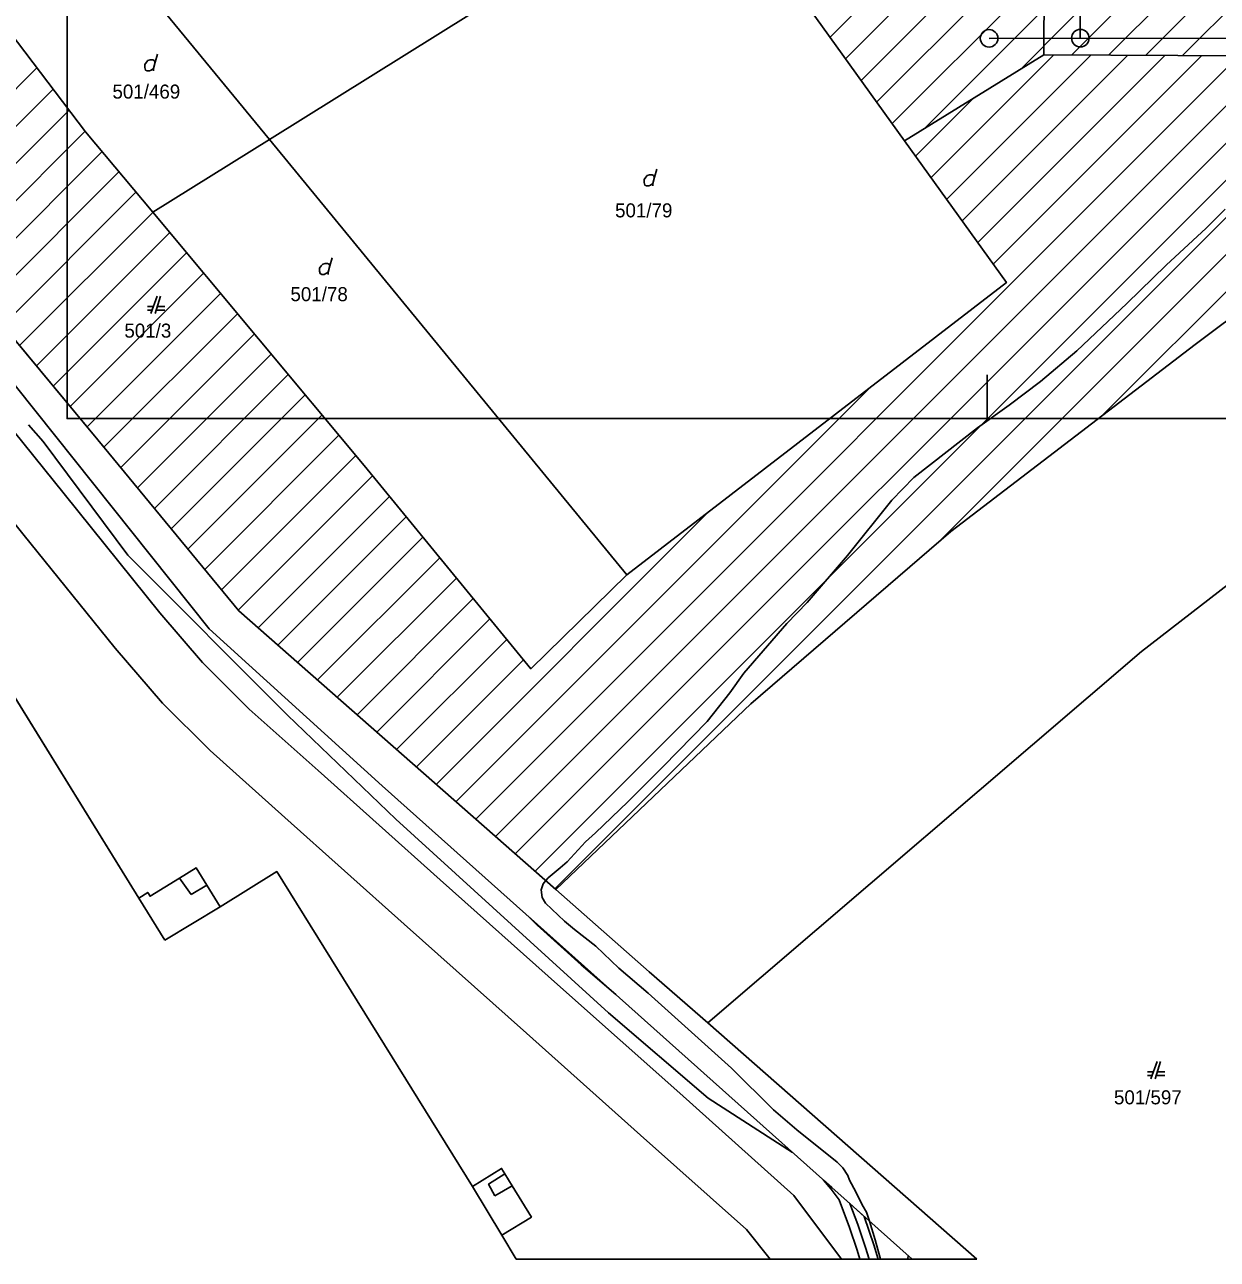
# Model space of a CAD drawing. Extents: x -264309 to -263505, y -1242443 to -1241763.
# Drawn here: x -264215.7 to -264079.6, y -1242443.4 to -1242302.6 of the extents above; entities that cross this region are included whole.
import ezdxf

# ---------------------------------------------------------------- set-up
doc = ezdxf.new("R2010")
doc.units = 0
for name, color, linetype in [('KFA_DAZDOVA_KANALIZACIA_vetva_D', 7, 'Continuous'), ('KFA_DAZDOVA_KANALIZACIA_vetva_F', 7, 'Continuous'), ('KN_2019_08_16', 7, 'Continuous'), ('KN_2019_08_16_KLADPAR', 7, 'Continuous'), ('KN_2019_08_16_ZAPPAR', 7, 'Continuous'), ('RAM_NA_TLAC_10xA4_1-500', 7, 'Continuous'), ('SRAFY_PARCELY', 7, 'Continuous')]:
    doc.layers.add(name, color=color, linetype=linetype)

msp = doc.modelspace()

# ---------------------------------------------------------------- linework, layer by layer
at = {"layer": 'KFA_DAZDOVA_KANALIZACIA_vetva_D'}
msp.add_lwpolyline([(-263821.59, -1242304.45), (-263853.82, -1242304.12), (-263903.79, -1242304.32), (-263951.83, -1242303.9), (-264004.17, -1242304.05), (-264044.82, -1242304.22), (-264095.21, -1242304.15), (-264105.62, -1242304.17)], dxfattribs=at)
for centre in [(-264105.62, -1242304.17), (-264095.21, -1242304.15)]:
    msp.add_circle(centre, 1, dxfattribs=at)
at = {"layer": 'KFA_DAZDOVA_KANALIZACIA_vetva_F'}
msp.add_lwpolyline([(-264123.84, -1242298.32), (-264095.25, -1242298.17), (-264095.21, -1242304.15)], dxfattribs=at)
at = {"layer": 'KN_2019_08_16'}
for points in [[(-264119.28, -1242439.08), (-264119.6, -1242438.07), (-264120.12, -1242437.23), (-264120.84, -1242435.74), (-264121.56, -1242434.41), (-264121.75, -1242433.87), (-264122.32, -1242433.02), (-264122.94, -1242432.35), (-264127.57, -1242428.67), (-264130.23, -1242426.38), (-264135.02, -1242421.64), (-264144.52, -1242413.09), (-264147.87, -1242410.23), (-264150.5, -1242407.72), (-264152.93, -1242405.83), (-264154.08, -1242404.89), (-264156.24, -1242402.81), (-264156.6, -1242402.17), (-264156.73, -1242401.31), (-264156.51, -1242400.61), (-264156.21, -1242400.25), (-264155.92, -1242399.93), (-264154.58, -1242398.8), (-264153.78, -1242398.09), (-264151.67, -1242395.84), (-264150.54, -1242394.8), (-264146.83, -1242391.28), (-264142.81, -1242387.25), (-264137.8, -1242382.11), (-264135.2, -1242378.82), (-264133.61, -1242376.59), (-264128.69, -1242370.91), (-264126.36, -1242368.51), (-264121.76, -1242363.16), (-264116.7, -1242356.85), (-264114.2, -1242354.26), (-264106.94, -1242348.61), (-264103.34, -1242346.03), (-264099.74, -1242343.3), (-264095.59, -1242339.81), (-264089.92, -1242334.43), (-264085.4, -1242330.05), (-264080.85, -1242325.81), (-264078.68, -1242323.64)], [(-264128.04, -1242431.26), (-264137.67, -1242425.08), (-264149.03, -1242415.35), (-264173.32, -1242393.23), (-264185.68, -1242381.36), (-264203.89, -1242363.13), (-264213.57, -1242350.16), (-264215.24, -1242348.24)], [(-264120.36, -1242443.45), (-264120.66, -1242442.41), (-264121.53, -1242439.81), (-264122.74, -1242436.68), (-264123.65, -1242435.44), (-264124.5, -1242434.42), (-264123.56, -1242435.26), (-264121.52, -1242437.08), (-264119.87, -1242438.56), (-264118.76, -1242441.81), (-264118.28, -1242443.45)], [(-264119.32, -1242443.45), (-264119.71, -1242442.11), (-264120.59, -1242439.47), (-264121.52, -1242437.08)], [(-264118, -1242443.45), (-264118.6, -1242441.21), (-264119.28, -1242439.08)], [(-264114.9, -1242443.45), (-264114.86, -1242443.03)]]:
    msp.add_lwpolyline(points, dxfattribs=at)
msp.add_lwpolyline([(-264148.21, -1242413.25), (-264152.18, -1242409.86), (-264157.18, -1242405.35), (-264158.21, -1242404.32)], close=True, dxfattribs=at)
at = {"layer": 'KN_2019_08_16_KLADPAR'}
for p, q in [((-264200.79, -1242306.88), (-264200.52, -1242305.98)), ((-264240.46, -1242310.08), (-264207.32, -1242349.97)), ((-264194.62, -1242371.54), (-264240.44, -1242314.08)), ((-264240.44, -1242314.08), (-264194.62, -1242371.54)), ((-264143.81, -1242320), (-264143.54, -1242319.1)), ((-264180.85, -1242330.11), (-264180.58, -1242329.21)), ((-264200.56, -1242333.56), (-264201.26, -1242335.56)), ((-264200.76, -1242335.56), (-264200.16, -1242333.56)), ((-264200.98, -1242334.76), (-264201.66, -1242334.76)), ((-264199.66, -1242334.76), (-264200.52, -1242334.76)), ((-264201.66, -1242335.16), (-264201.12, -1242335.16)), ((-264200.64, -1242335.16), (-264199.66, -1242335.16)), ((-264207.32, -1242349.97), (-264191.23, -1242369.48)), ((-264202.64, -1242402.25), (-264234.16, -1242351.24)), ((-264191.23, -1242369.48), (-264155.07, -1242401.25)), ((-264174.88, -1242389.44), (-264194.62, -1242371.54)), ((-264194.62, -1242371.54), (-264174.88, -1242389.44)), ((-264123.56, -1242435.26), (-264174.88, -1242389.44)), ((-264174.88, -1242389.44), (-264123.56, -1242435.26)), ((-264196.09, -1242398.8), (-264198, -1242399.97)), ((-264194.88, -1242400.75), (-264196.09, -1242398.8)), ((-264186.9, -1242399.22), (-264193.34, -1242403.23)), ((-264164.58, -1242435.14), (-264186.9, -1242399.22)), ((-264198, -1242399.97), (-264201.36, -1242402.03)), ((-264193.34, -1242403.23), (-264194.88, -1242400.75)), ((-264155.07, -1242401.25), (-264144.39, -1242410.64)), ((-264201.63, -1242401.6), (-264202.64, -1242402.25)), ((-264201.36, -1242402.03), (-264201.63, -1242401.6)), ((-264144.39, -1242410.64), (-264137.73, -1242416.49)), ((-264137.73, -1242416.49), (-264107.02, -1242443.45)), ((-264086.45, -1242420.88), (-264087.15, -1242422.88)), ((-264086.65, -1242422.88), (-264086.05, -1242420.88)), ((-264086.87, -1242422.08), (-264087.55, -1242422.08)), ((-264085.55, -1242422.08), (-264086.41, -1242422.08)), ((-264087.55, -1242422.48), (-264087.01, -1242422.48)), ((-264086.53, -1242422.48), (-264085.55, -1242422.48)), ((-264161.25, -1242433.08), (-264164.58, -1242435.14)), ((-264160.87, -1242433.7), (-264161.25, -1242433.08)), ((-264160.03, -1242435.07), (-264160.87, -1242433.7)), ((-264157.85, -1242438.64), (-264160.03, -1242435.07)), ((-264114.39, -1242443.45), (-264123.56, -1242435.26)), ((-264123.56, -1242435.26), (-264114.39, -1242443.45)), ((-264161.23, -1242440.7), (-264157.85, -1242438.64)), ((-264159.6, -1242443.45), (-264161.23, -1242440.7)), ((-264114.39, -1242443.45), (-264159.6, -1242443.45)), ((-264107.02, -1242443.45), (-264114.39, -1242443.45))]:
    msp.add_line(p, q, dxfattribs=at)
for points in [[(-264212.29, -1242180.92), (-264215.03, -1242177.17), (-264211.96, -1242175.6), (-264195.05, -1242168.92), (-264177.6, -1242192.97), (-264074.04, -1242162.41), (-264070.8, -1242196.19), (-264098.84, -1242196.05), (-264099.36, -1242306.05), (-264115.27, -1242315.84), (-264137.78, -1242284.52)], [(-264264.01, -1242217.15), (-264233.51, -1242192.88), (-264212.29, -1242180.92), (-264137.78, -1242284.52), (-264187.74, -1242315.7), (-264213.92, -1242283.84)], [(-263950.84, -1242196.76), (-263951.29, -1242290.6), (-263951.37, -1242306.76), (-264045.86, -1242306.31), (-264099.36, -1242306.05), (-264098.84, -1242196.05), (-264070.8, -1242196.19)], [(-264187.74, -1242315.7), (-264201.06, -1242324.01), (-264208.73, -1242314.82), (-264233.72, -1242281.89), (-264276.4, -1242228.3), (-264264.01, -1242217.15), (-264213.92, -1242283.84)], [(-264187.74, -1242315.7), (-264137.78, -1242284.52), (-264115.27, -1242315.84), (-264103.64, -1242332.03), (-264146.94, -1242365.35)], [(-264187.74, -1242315.7), (-264146.94, -1242365.35), (-264157.91, -1242376.09), (-264176.92, -1242352.91), (-264201.06, -1242324.01)]]:
    msp.add_lwpolyline(points, close=True, dxfattribs=at)
for points in [[(-264155.07, -1242401.25), (-264191.23, -1242369.48), (-264207.32, -1242349.97), (-264240.46, -1242310.08), (-264272.98, -1242263.62)], [(-264233.72, -1242281.89), (-264208.73, -1242314.82), (-264201.06, -1242324.01), (-264176.92, -1242352.91), (-264157.91, -1242376.09), (-264146.94, -1242365.35), (-264103.64, -1242332.03), (-264115.27, -1242315.84), (-264099.36, -1242306.05), (-264045.86, -1242306.31)], [(-264200.97, -1242307.87), (-264200.97, -1242307.6), (-264200.79, -1242306.88), (-264200.88, -1242306.7), (-264201.06, -1242306.61), (-264201.33, -1242306.61), (-264201.6, -1242306.7), (-264201.78, -1242306.88), (-264201.96, -1242307.15), (-264201.96, -1242307.51), (-264201.87, -1242307.78), (-264201.69, -1242307.87), (-264201.42, -1242307.87), (-264201.24, -1242307.78), (-264200.97, -1242307.6)], [(-264143.99, -1242320.99), (-264143.99, -1242320.72), (-264143.81, -1242320), (-264143.9, -1242319.82), (-264144.08, -1242319.73), (-264144.35, -1242319.73), (-264144.62, -1242319.82), (-264144.8, -1242320), (-264144.98, -1242320.27), (-264144.98, -1242320.63), (-264144.89, -1242320.9), (-264144.71, -1242320.99), (-264144.44, -1242320.99), (-264144.26, -1242320.9), (-264143.99, -1242320.72)], [(-264155.07, -1242401.25), (-264132.82, -1242380.09), (-264109.99, -1242360.41), (-264082.11, -1242339.09), (-264061.82, -1242323.92)], [(-264061.82, -1242323.92), (-264082.11, -1242339.09), (-264109.99, -1242360.41), (-264132.82, -1242380.09), (-264155.07, -1242401.25)], [(-264181.03, -1242331.1), (-264181.03, -1242330.83), (-264180.85, -1242330.11), (-264180.94, -1242329.93), (-264181.12, -1242329.84), (-264181.39, -1242329.84), (-264181.66, -1242329.93), (-264181.84, -1242330.11), (-264182.02, -1242330.38), (-264182.02, -1242330.74), (-264181.93, -1242331.01), (-264181.75, -1242331.1), (-264181.48, -1242331.1), (-264181.3, -1242331.01), (-264181.03, -1242330.83)], [(-264234.16, -1242351.24), (-264202.64, -1242402.25), (-264201.63, -1242401.6), (-264201.36, -1242402.03), (-264198, -1242399.97), (-264196.09, -1242398.8), (-264194.88, -1242400.75), (-264193.34, -1242403.23), (-264186.9, -1242399.22), (-264164.58, -1242435.14), (-264161.25, -1242433.08), (-264160.87, -1242433.7), (-264160.03, -1242435.07), (-264157.85, -1242438.64), (-264161.23, -1242440.7), (-264159.6, -1242443.45)], [(-264069.2, -1242359.38), (-264088.24, -1242374.12), (-264137.73, -1242416.49)], [(-264137.73, -1242416.49), (-264088.24, -1242374.12), (-264069.2, -1242359.38)], [(-264137.73, -1242416.49), (-264144.39, -1242410.64), (-264155.07, -1242401.25)], [(-264107.02, -1242443.45), (-264137.73, -1242416.49)]]:
    msp.add_lwpolyline(points, dxfattribs=at)
at = {"layer": 'KN_2019_08_16_ZAPPAR'}
for p, q in [((-264195.36, -1242375.35), (-264190.05, -1242380.7)), ((-264199.94, -1242380), (-264194.5, -1242385.4)), ((-264196.66, -1242401.83), (-264198, -1242399.97)), ((-264194.88, -1242400.75), (-264196.66, -1242401.83)), ((-264202.64, -1242402.25), (-264199.69, -1242407.03)), ((-264199.69, -1242407.03), (-264193.34, -1242403.23)), ((-264164.58, -1242435.14), (-264161.23, -1242440.7)), ((-264162.01, -1242436.2), (-264160.03, -1242435.07))]:
    msp.add_line(p, q, dxfattribs=at)
for points in [[(-264243.73, -1242315.98), (-264233.3, -1242328.8), (-264221.58, -1242343.23), (-264211.15, -1242356.14), (-264200.23, -1242369.71), (-264195.36, -1242375.35)], [(-264248.85, -1242319.92), (-264237.43, -1242334.06), (-264226.65, -1242347.31), (-264215.86, -1242360.68), (-264205.35, -1242373.72), (-264199.94, -1242380)], [(-264190.05, -1242380.7), (-264182.19, -1242387.69), (-264168.24, -1242400.15), (-264154.53, -1242412.39), (-264140.92, -1242424.51), (-264127.91, -1242436.18), (-264122.47, -1242443.45)], [(-264194.5, -1242385.4), (-264185.99, -1242393.04), (-264172.36, -1242405.23), (-264158.42, -1242417.65), (-264145.39, -1242429.27), (-264133.3, -1242440.05), (-264130.6, -1242443.45)], [(-264160.87, -1242433.7), (-264162.74, -1242434.87), (-264162.01, -1242436.2)]]:
    msp.add_lwpolyline(points, dxfattribs=at)
at = {"layer": 'RAM_NA_TLAC_10xA4_1-500'}
msp.add_line((-264105.83, -1242342.54), (-264105.83, -1242347.54), dxfattribs=at)
msp.add_lwpolyline([(-264210.83, -1242050.54), (-264105.83, -1242050.54), (-264000.83, -1242050.54), (-263895.83, -1242050.54), (-263790.83, -1242050.54), (-263685.83, -1242050.54), (-263685.83, -1242199.04), (-263685.83, -1242347.54), (-263790.83, -1242347.54), (-263895.83, -1242347.54), (-264000.83, -1242347.54), (-264105.83, -1242347.54), (-264210.83, -1242347.54), (-264210.83, -1242199.04)], close=True, dxfattribs=at)
at = {"layer": 'SRAFY_PARCELY'}
for p, q in [((-264099.35, -1242304.97), (-263990.95, -1242196.57)), ((-264096.2, -1242306.07), (-263986.73, -1242196.59)), ((-264091.98, -1242306.09), (-263982.5, -1242196.61)), ((-264087.76, -1242306.11), (-263978.28, -1242196.63)), ((-264083.54, -1242306.13), (-263974.06, -1242196.65)), ((-264123.77, -1242304.02), (-264099.23, -1242279.49)), ((-264121.99, -1242306.49), (-264099.25, -1242283.75)), ((-264120.22, -1242308.96), (-264099.27, -1242288.01)), ((-264118.44, -1242311.42), (-264099.29, -1242292.28)), ((-264116.67, -1242313.89), (-264099.32, -1242296.54)), ((-264112.94, -1242314.41), (-264099.34, -1242300.8)), ((-264101.91, -1242307.62), (-264099.36, -1242305.06)), ((-264164.19, -1242393.23), (-264077.12, -1242306.16)), ((-264161.94, -1242395.22), (-264072.9, -1242306.18)), ((-264159.68, -1242397.2), (-264068.67, -1242306.2)), ((-264157.42, -1242399.19), (-264064.45, -1242306.22)), ((-264155.16, -1242401.17), (-264060.23, -1242306.24)), ((-264112.24, -1242320.06), (-264098.23, -1242306.06)), ((-264111.2, -1242361.45), (-264056.01, -1242306.26)), ((-264110.46, -1242322.53), (-264094.01, -1242306.08)), ((-264108.69, -1242325), (-264089.78, -1242306.1)), ((-264106.92, -1242327.47), (-264085.56, -1242306.12)), ((-264105.14, -1242329.94), (-264081.34, -1242306.14)), ((-264092.67, -1242347.16), (-264051.79, -1242306.28)), ((-264229.73, -1242323), (-264214.26, -1242307.53)), ((-264227.8, -1242325.32), (-264212.43, -1242309.95)), ((-264114.01, -1242317.59), (-264107.43, -1242311.02)), ((-264225.88, -1242327.64), (-264210.6, -1242312.36)), ((-264223.95, -1242329.95), (-264208.77, -1242314.77)), ((-264222.02, -1242332.27), (-264206.84, -1242317.09)), ((-264220.1, -1242334.59), (-264204.91, -1242319.4)), ((-264218.17, -1242336.91), (-264202.98, -1242321.71)), ((-264216.25, -1242339.22), (-264201.05, -1242324.02)), ((-264214.32, -1242341.54), (-264199.12, -1242326.33)), ((-264212.4, -1242343.86), (-264197.19, -1242328.65)), ((-264210.47, -1242346.17), (-264195.26, -1242330.96)), ((-264208.55, -1242348.49), (-264193.33, -1242333.27)), ((-264206.63, -1242350.81), (-264191.39, -1242335.58)), ((-264204.71, -1242353.14), (-264189.46, -1242337.89)), ((-264202.79, -1242355.46), (-264187.53, -1242340.2)), ((-264200.87, -1242357.79), (-264185.6, -1242342.52)), ((-264198.96, -1242360.11), (-264183.67, -1242344.83)), ((-264166.45, -1242391.25), (-264119.23, -1242344.03)), ((-264197.04, -1242362.44), (-264181.74, -1242347.14)), ((-264195.12, -1242364.76), (-264179.81, -1242349.45)), ((-264193.2, -1242367.09), (-264177.88, -1242351.76)), ((-264191.29, -1242369.41), (-264175.96, -1242354.08)), ((-264189.04, -1242371.41), (-264174.04, -1242356.42)), ((-264186.78, -1242373.39), (-264172.13, -1242358.75)), ((-264168.71, -1242389.27), (-264137.64, -1242358.19)), ((-264184.52, -1242375.38), (-264170.22, -1242361.08)), ((-264182.26, -1242377.36), (-264168.31, -1242363.41)), ((-264180, -1242379.34), (-264166.4, -1242365.74)), ((-264177.74, -1242381.33), (-264164.49, -1242368.07)), ((-264175.49, -1242383.31), (-264162.58, -1242370.4)), ((-264173.23, -1242385.3), (-264160.66, -1242372.73)), ((-264170.97, -1242387.28), (-264158.75, -1242375.06))]:
    msp.add_line(p, q, dxfattribs=at)

# ---------------------------------------------------------------- texts
at = {"layer": 'KN_2019_08_16_KLADPAR'}
for s, p in [('501/469', (-264205.65, -1242311.04)), ('501/79', (-264148.3, -1242324.59)), ('501/78', (-264185.34, -1242334.15)), ('501/3', (-264204.29, -1242338.31)), ('501/597', (-264091.37, -1242425.77))]:
    msp.add_text(s, height=1.6, dxfattribs=at).set_placement(p)

doc.saveas('drawing.dxf')
